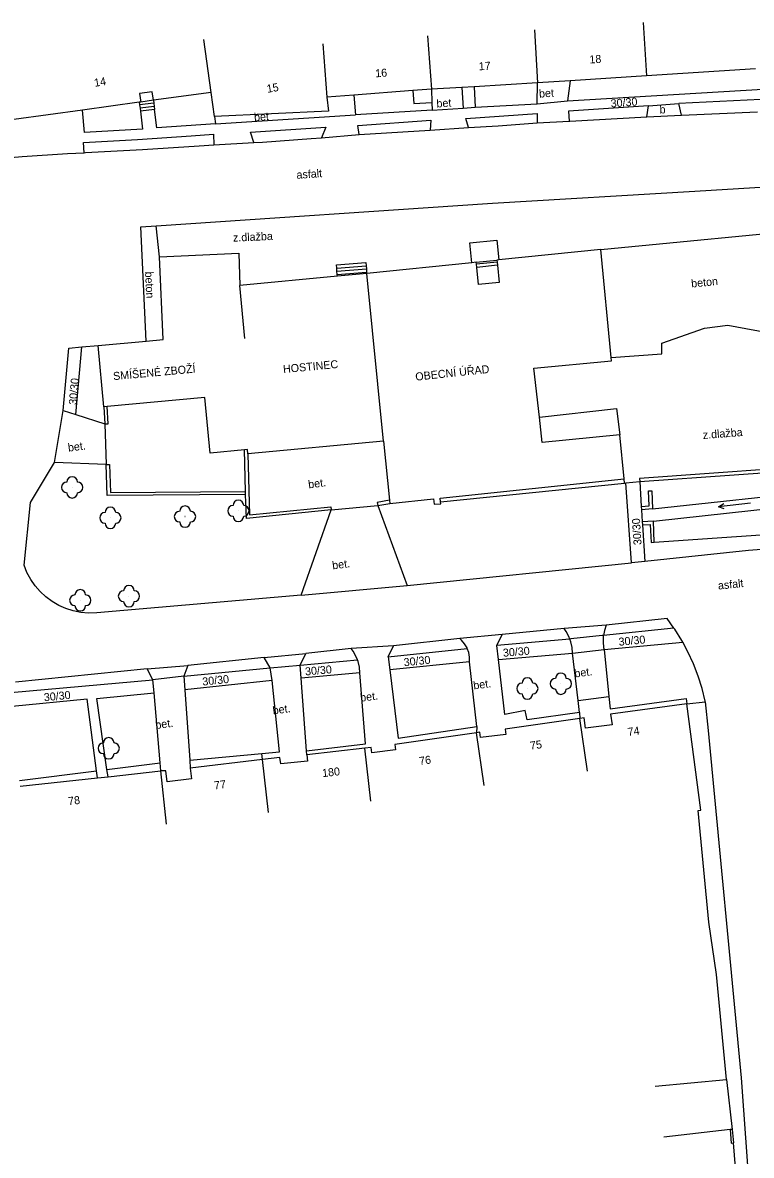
# Model space of a CAD drawing. Extents: x -544674 to -541478, y -1199076 to -1195527.
# Drawn here: x -541857.3 to -541789, y -1198842.7 to -1198736.5 of the extents above; entities that cross this region are included whole.
import ezdxf

# ---------------------------------------------------------------- set-up
doc = ezdxf.new("R2010")
doc.units = 0
for name, color, linetype in [('BUDOVY_MĚŘ', 7, 'Continuous'), ('POMOC_POPIS', 7, 'Continuous'), ('ROZHRANÍ_PLOCH', 7, 'Continuous'), ('ZELEŇ', 7, 'Continuous'), ('ZN_DOPLŇKOVÉ', 7, 'Continuous'), ('ZN_KULTUR', 7, 'Continuous'), ('Č_POPIS_ORIENT', 7, 'Continuous')]:
    doc.layers.add(name, color=color, linetype=linetype)

msp = doc.modelspace()

# ---------------------------------------------------------------- linework, layer by layer
at = {"layer": 'BUDOVY_MĚŘ'}
for points in [[(-541799.16, -1198736.54), (-541798.84, -1198741.53)], [(-541809.36, -1198737.2), (-541809.06, -1198742.19)], [(-541839.64, -1198743.08), (-541840.32, -1198738.13)], [(-541829.17, -1198738.53), (-541828.79, -1198743.52)], [(-541819.37, -1198737.79), (-541818.99, -1198742.78)], [(-541798.84, -1198741.53), (-541805.99, -1198741.99)], [(-541820.75, -1198742.91), (-541826.28, -1198743.33)], [(-541818.99, -1198742.78), (-541820.75, -1198742.91)], [(-541816.15, -1198742.61), (-541818.99, -1198742.78)], [(-541814.99, -1198742.54), (-541816.15, -1198742.61)], [(-541809.06, -1198742.19), (-541814.99, -1198742.54)], [(-541805.99, -1198741.99), (-541809.06, -1198742.19)], [(-541846.38, -1198744), (-541851.69, -1198744.73)], [(-541846.24, -1198743.98), (-541846.38, -1198744)], [(-541845.05, -1198743.82), (-541845.16, -1198743.03), (-541846.35, -1198743.19), (-541846.24, -1198743.98)], [(-541845.05, -1198743.82), (-541846.24, -1198743.98)], [(-541839.64, -1198743.08), (-541845.05, -1198743.82)], [(-541839.33, -1198745.35), (-541839.64, -1198743.08)], [(-541828.79, -1198743.52), (-541828.64, -1198744.85), (-541839.33, -1198745.35)], [(-541826.28, -1198743.33), (-541828.79, -1198743.52)], [(-541851.69, -1198744.73), (-541858.14, -1198745.62)], [(-541803.12, -1198757.8), (-541812.69, -1198758.78)], [(-541802.17, -1198767.94), (-541803.12, -1198757.8)], [(-541845.74, -1198766.38), (-541844.14, -1198766.23), (-541844.48, -1198758.49)], [(-541844.48, -1198758.49), (-541837.06, -1198758.16), (-541836.95, -1198761.17)], [(-541812.69, -1198758.78), (-541812.87, -1198758.8)], [(-541812.87, -1198758.8), (-541812.85, -1198758.99)], [(-541815.22, -1198759.04), (-541825.06, -1198760.04)], [(-541814.8, -1198759), (-541815.22, -1198759.04)], [(-541814.78, -1198759.18), (-541814.8, -1198759)], [(-541814.75, -1198759.48), (-541814.78, -1198759.18)], [(-541812.82, -1198759.28), (-541812.65, -1198760.9), (-541814.58, -1198761.09), (-541814.75, -1198759.48)], [(-541812.85, -1198758.99), (-541812.82, -1198759.28)], [(-541827.81, -1198760.3), (-541836.95, -1198761.17)], [(-541825.06, -1198760.04), (-541827.81, -1198760.3)], [(-541823.49, -1198775.77), (-541825.06, -1198760.04)], [(-541836.48, -1198766.15), (-541836.95, -1198761.17)], [(-541850.23, -1198766.8), (-541845.74, -1198766.38)], [(-541849.69, -1198772.55), (-541850.23, -1198766.8)], [(-541808.89, -1198773.51), (-541809.41, -1198768.92), (-541802.14, -1198768.24), (-541802.17, -1198767.94)], [(-541849.39, -1198772.52), (-541849.69, -1198772.55)], [(-541836.52, -1198776.59), (-541839.73, -1198776.89), (-541840.22, -1198771.67), (-541849.39, -1198772.52)], [(-541801.36, -1198775.18), (-541808.62, -1198775.9), (-541808.89, -1198773.51)], [(-541823.49, -1198775.77), (-541836.21, -1198776.96)], [(-541823.49, -1198775.77), (-541822.93, -1198781.3)], [(-541800.95, -1198779.3), (-541801.36, -1198775.18)], [(-541836.21, -1198776.96), (-541836.25, -1198776.56), (-541836.52, -1198776.59)], [(-541818.15, -1198781.46), (-541818.19, -1198781.1), (-541800.95, -1198779.3)], [(-541822.9, -1198781.6), (-541818.81, -1198781.17), (-541818.75, -1198781.68), (-541818.13, -1198781.63), (-541818.15, -1198781.46)], [(-541822.93, -1198781.3), (-541822.9, -1198781.6)], [(-541795.07, -1198800.4), (-541802.22, -1198801.36), (-541802.08, -1198802.35), (-541804.56, -1198802.68), (-541804.69, -1198801.69), (-541805.09, -1198801.75)], [(-541791.35, -1198835.59), (-541792.29, -1198825.76), (-541793.02, -1198820.86), (-541794, -1198810.37), (-541793.75, -1198810.34), (-541795.07, -1198800.4)], [(-541805.09, -1198801.75), (-541812.1, -1198802.76), (-541812.03, -1198803.25), (-541814.4, -1198803.54), (-541814.47, -1198803.05), (-541814.77, -1198803.09)], [(-541804.38, -1198806.7), (-541805.09, -1198801.75)], [(-541814.77, -1198803.09), (-541822.43, -1198804.19), (-541822.36, -1198804.69), (-541824.59, -1198804.97), (-541824.64, -1198804.47), (-541825.24, -1198804.54)], [(-541814.06, -1198808.04), (-541814.77, -1198803.09)], [(-541825.24, -1198804.54), (-541830.69, -1198805.17)], [(-541824.67, -1198809.51), (-541825.24, -1198804.54)], [(-541834.82, -1198805.59), (-541841.6, -1198806.43)], [(-541830.69, -1198805.17), (-541830.62, -1198805.77), (-541833.12, -1198806.01), (-541833.19, -1198805.41), (-541834.82, -1198805.59)], [(-541834.27, -1198810.56), (-541834.82, -1198805.59)], [(-541849.3, -1198807.22), (-541844.36, -1198806.68)], [(-541841.6, -1198806.43), (-541841.48, -1198807.42), (-541843.76, -1198807.69), (-541843.89, -1198806.65), (-541844.36, -1198806.68)], [(-541843.82, -1198811.65), (-541844.36, -1198806.68)], [(-541857.54, -1198808.11), (-541850.3, -1198807.33)], [(-541850.3, -1198807.33), (-541849.3, -1198807.22)], [(-541798.03, -1198836.23), (-541791.35, -1198835.59)], [(-541791.35, -1198835.59), (-541790.81, -1198840.27)], [(-541791.01, -1198840.29), (-541797.23, -1198841.01)], [(-541790.81, -1198840.27), (-541791.01, -1198840.29)]]:
    msp.add_lwpolyline(points, dxfattribs=at)
at = {"layer": 'ROZHRANÍ_PLOCH'}
for points in [[(-541820.75, -1198742.91), (-541820.66, -1198744.13), (-541818.95, -1198744.03)], [(-541818.99, -1198742.78), (-541818.95, -1198744.03)], [(-541816.15, -1198742.61), (-541816.03, -1198744.54)], [(-541814.99, -1198742.54), (-541814.9, -1198744.46)], [(-541809.08, -1198744.15), (-541809.06, -1198742.19)], [(-541805.99, -1198741.99), (-541806.25, -1198743.88)], [(-541806.25, -1198743.88), (-541787.96, -1198742.78)], [(-541846.38, -1198744), (-541846.34, -1198744.25)], [(-541845.05, -1198743.82), (-541845.02, -1198744.09)], [(-541826.28, -1198743.33), (-541826.12, -1198745.19)], [(-541818.95, -1198744.03), (-541818.93, -1198744.73)], [(-541809.08, -1198744.15), (-541806.25, -1198743.88)], [(-541788.15, -1198743.74), (-541795.83, -1198744.13)], [(-541846.26, -1198744.84), (-541846.06, -1198746.52), (-541851.52, -1198746.84), (-541851.69, -1198744.73)], [(-541845.02, -1198744.09), (-541846.34, -1198744.25)], [(-541846.34, -1198744.25), (-541846.3, -1198744.54)], [(-541844.98, -1198744.39), (-541846.3, -1198744.54)], [(-541846.3, -1198744.54), (-541846.26, -1198744.84)], [(-541844.94, -1198744.68), (-541846.26, -1198744.84)], [(-541845.02, -1198744.09), (-541844.98, -1198744.39)], [(-541844.98, -1198744.39), (-541844.94, -1198744.68)], [(-541839.22, -1198746.03), (-541844.74, -1198746.39), (-541844.94, -1198744.68)], [(-541818.93, -1198744.73), (-541826.12, -1198745.19)], [(-541818.93, -1198744.73), (-541816.03, -1198744.54)], [(-541816.03, -1198744.54), (-541814.9, -1198744.46)], [(-541815.53, -1198746.38), (-541815.78, -1198745.52), (-541809.11, -1198745.05), (-541809.09, -1198745.93)], [(-541814.9, -1198744.46), (-541809.08, -1198744.15)], [(-541798.66, -1198744.34), (-541806.15, -1198744.85), (-541806.09, -1198745.77)], [(-541798.81, -1198745.36), (-541798.66, -1198744.34)], [(-541798.66, -1198744.34), (-541795.83, -1198744.13)], [(-541795.56, -1198745.22), (-541795.83, -1198744.13)], [(-541795.56, -1198745.22), (-541788.46, -1198744.89)], [(-541839.33, -1198745.35), (-541839.22, -1198746.03)], [(-541839.22, -1198746.03), (-541826.12, -1198745.19)], [(-541825.76, -1198747.01), (-541825.9, -1198746.17), (-541819.07, -1198745.68), (-541819.11, -1198746.61)], [(-541815.53, -1198746.38), (-541812.76, -1198746.2), (-541809.09, -1198745.93)], [(-541809.09, -1198745.93), (-541806.09, -1198745.77)], [(-541806.09, -1198745.77), (-541806.02, -1198745.77), (-541798.81, -1198745.36)], [(-541798.81, -1198745.36), (-541795.56, -1198745.22)], [(-541851.55, -1198748.73), (-541851.59, -1198747.77), (-541846.55, -1198747.5), (-541841.52, -1198747.15), (-541839.42, -1198746.98), (-541839.4, -1198747.98)], [(-541835.64, -1198747.78), (-541835.96, -1198746.79), (-541828.9, -1198746.35), (-541829.29, -1198747.32)], [(-541829.29, -1198747.32), (-541825.76, -1198747.01)], [(-541825.76, -1198747.01), (-541819.11, -1198746.61)], [(-541819.11, -1198746.61), (-541815.53, -1198746.38)], [(-541851.55, -1198748.73), (-541851.4, -1198748.72), (-541846.08, -1198748.44), (-541840.76, -1198748.08), (-541839.4, -1198747.98)], [(-541839.4, -1198747.98), (-541835.64, -1198747.78)], [(-541835.64, -1198747.78), (-541834.84, -1198747.74), (-541830.28, -1198747.41), (-541829.29, -1198747.32)], [(-541867.92, -1198750.18), (-541865.85, -1198749.92), (-541861.61, -1198749.47), (-541857.36, -1198749.1), (-541853.1, -1198748.81), (-541851.55, -1198748.73)], [(-541844.79, -1198755.59), (-541813.27, -1198753.45), (-541794.31, -1198752.32), (-541783.08, -1198751.66)], [(-541845.74, -1198766.38), (-541846.22, -1198755.69), (-541844.79, -1198755.59)], [(-541844.48, -1198758.49), (-541844.79, -1198755.59)], [(-541803.12, -1198757.8), (-541781.8, -1198755.74)], [(-541815.22, -1198759.04), (-541815.41, -1198757.19), (-541812.88, -1198756.93), (-541812.69, -1198758.78)], [(-541814.8, -1198759), (-541812.87, -1198758.8)], [(-541827.88, -1198759.54), (-541827.91, -1198759.24), (-541825.16, -1198759.02), (-541825.13, -1198759.32)], [(-541827.88, -1198759.54), (-541825.13, -1198759.32)], [(-541827.85, -1198759.84), (-541827.88, -1198759.54)], [(-541827.85, -1198759.84), (-541825.1, -1198759.62)], [(-541827.82, -1198760.14), (-541827.85, -1198759.84)], [(-541827.82, -1198760.14), (-541825.07, -1198759.92)], [(-541825.13, -1198759.32), (-541825.1, -1198759.62)], [(-541825.1, -1198759.62), (-541825.07, -1198759.92)], [(-541825.07, -1198759.92), (-541825.06, -1198760.04)], [(-541812.85, -1198758.99), (-541814.78, -1198759.18)], [(-541812.82, -1198759.28), (-541814.75, -1198759.48)], [(-541827.81, -1198760.3), (-541827.82, -1198760.14)], [(-541802.17, -1198767.94), (-541797.43, -1198767.58), (-541797.4, -1198766.58), (-541793.42, -1198765.18), (-541791.22, -1198764.9), (-541786.68, -1198765.73), (-541786.58, -1198767.24), (-541780.84, -1198767.12)], [(-541853.49, -1198772.88), (-541852.98, -1198767.05), (-541851.77, -1198766.94)], [(-541852.32, -1198773.26), (-541851.77, -1198766.94)], [(-541851.77, -1198766.94), (-541850.23, -1198766.8)], [(-541808.89, -1198773.51), (-541801.67, -1198772.7), (-541801.36, -1198775.18)], [(-541854.32, -1198777.78), (-541853.49, -1198772.88)], [(-541853.49, -1198772.88), (-541852.32, -1198773.26)], [(-541852.32, -1198773.26), (-541849.6, -1198774.15)], [(-541849.6, -1198774.15), (-541849.47, -1198777.95)], [(-541831.21, -1198790.19), (-541850.36, -1198791.87), (-541851.13, -1198791.89), (-541851.85, -1198791.82), (-541852.56, -1198791.68), (-541853.26, -1198791.46), (-541853.92, -1198791.16), (-541854.55, -1198790.8), (-541855.13, -1198790.36), (-541855.67, -1198789.87), (-541856.14, -1198789.32), (-541856.55, -1198788.72), (-541856.9, -1198788.08), (-541857.17, -1198787.4), (-541856.56, -1198781.51), (-541854.32, -1198777.78)], [(-541849.47, -1198777.95), (-541854.32, -1198777.78)], [(-541710.2, -1198778.44), (-541725.87, -1198780), (-541761.28, -1198783.4), (-541783.3, -1198785.55), (-541789.31, -1198786.01), (-541799.01, -1198787.05)], [(-541818.15, -1198781.46), (-541800.91, -1198779.69)], [(-541800.91, -1198779.69), (-541800.95, -1198779.3)], [(-541800.91, -1198779.69), (-541800.8, -1198779.68)], [(-541800.8, -1198779.68), (-541799.49, -1198779.54)], [(-541800.27, -1198787.18), (-541800.8, -1198779.68)], [(-541799.49, -1198779.54), (-541799.34, -1198781.89)], [(-541831.21, -1198790.19), (-541828.39, -1198782.21)], [(-541828.39, -1198782.21), (-541824.03, -1198781.8)], [(-541824.03, -1198781.8), (-541821.27, -1198789.28)], [(-541799.34, -1198781.89), (-541799.32, -1198782.19)], [(-541799.32, -1198782.19), (-541799.25, -1198783.32)], [(-541799.25, -1198783.32), (-541799.23, -1198783.62)], [(-541799.23, -1198783.62), (-541799.01, -1198787.05)], [(-541821.27, -1198789.28), (-541800.27, -1198787.18)], [(-541799.01, -1198787.05), (-541800.27, -1198787.18)], [(-541831.21, -1198790.19), (-541821.27, -1198789.28)], [(-541796.28, -1198793.29), (-541796.93, -1198792.4), (-541802.62, -1198793)], [(-541812.36, -1198793.89), (-541816.33, -1198794.27)], [(-541812.86, -1198794.92), (-541812.36, -1198793.89)], [(-541806.58, -1198793.33), (-541812.36, -1198793.89)], [(-541802.62, -1198793), (-541806.58, -1198793.33)], [(-541806.03, -1198794.31), (-541806.12, -1198794.08), (-541806.37, -1198793.61), (-541806.58, -1198793.33)], [(-541802.62, -1198793), (-541802.8, -1198793.51), (-541802.89, -1198793.98)], [(-541796.28, -1198793.29), (-541802.89, -1198793.98)], [(-541795.46, -1198794.6), (-541795.55, -1198794.44), (-541796.21, -1198793.4), (-541796.28, -1198793.29)], [(-541822.57, -1198794.95), (-541826.53, -1198795.2)], [(-541823.04, -1198795.97), (-541822.57, -1198794.95)], [(-541816.33, -1198794.27), (-541822.57, -1198794.95)], [(-541815.64, -1198795.19), (-541815.66, -1198795.14), (-541815.89, -1198794.75), (-541816.18, -1198794.41), (-541816.33, -1198794.27)], [(-541806.03, -1198794.31), (-541812.86, -1198794.92)], [(-541812.71, -1198796.22), (-541812.86, -1198794.92)], [(-541802.89, -1198793.98), (-541802.99, -1198793.99), (-541805.95, -1198794.3), (-541806.03, -1198794.31)], [(-541805.8, -1198795.63), (-541805.83, -1198795.1), (-541805.93, -1198794.58), (-541806.03, -1198794.31)], [(-541802.89, -1198793.98), (-541802.9, -1198794.04), (-541802.92, -1198794.58), (-541802.87, -1198795.11), (-541802.83, -1198795.28)], [(-541802.83, -1198795.28), (-541795.46, -1198794.6)], [(-541793.34, -1198800.21), (-541793.35, -1198800.15), (-541793.64, -1198798.96), (-541794.01, -1198797.78), (-541794.45, -1198796.64), (-541794.97, -1198795.52), (-541795.46, -1198794.6)], [(-541834.66, -1198796.05), (-541841.82, -1198796.78)], [(-541834.66, -1198796.05), (-541830.78, -1198795.68)], [(-541834.12, -1198797), (-541834.66, -1198796.05)], [(-541831.3, -1198796.75), (-541830.78, -1198795.68)], [(-541826.53, -1198795.2), (-541830.78, -1198795.68)], [(-541825.94, -1198796.26), (-541826.07, -1198795.92), (-541826.34, -1198795.45), (-541826.53, -1198795.2)], [(-541823.04, -1198795.97), (-541815.64, -1198795.19)], [(-541823.04, -1198795.97), (-541822.89, -1198797.21)], [(-541815.44, -1198796.45), (-541815.44, -1198796), (-541815.51, -1198795.56), (-541815.64, -1198795.19)], [(-541812.71, -1198796.22), (-541805.8, -1198795.63)], [(-541805.8, -1198795.63), (-541802.83, -1198795.28)], [(-541805.26, -1198800.07), (-541805.8, -1198795.63)], [(-541802.83, -1198795.28), (-541802.37, -1198799.71)], [(-541845.65, -1198797.1), (-541857.97, -1198798.34)], [(-541845.65, -1198797.1), (-541841.82, -1198796.78)], [(-541845.1, -1198798.13), (-541845.65, -1198797.1)], [(-541841.82, -1198796.78), (-541842.2, -1198797.78)], [(-541842.2, -1198797.78), (-541834.12, -1198797)], [(-541834.12, -1198797), (-541831.3, -1198796.75)], [(-541833.91, -1198798.2), (-541834.12, -1198797)], [(-541831.3, -1198796.75), (-541825.94, -1198796.26)], [(-541831.21, -1198797.97), (-541831.3, -1198796.75)], [(-541825.71, -1198797.49), (-541825.75, -1198796.95), (-541825.88, -1198796.42), (-541825.94, -1198796.26)], [(-541815.44, -1198796.45), (-541822.89, -1198797.21)], [(-541814.75, -1198802.52), (-541815.44, -1198796.45)], [(-541805.12, -1198801.21), (-541810.04, -1198801.88), (-541810.21, -1198801.01), (-541812.13, -1198801.38), (-541812.71, -1198796.22)], [(-541858.42, -1198799.32), (-541845.1, -1198798.13)], [(-541842.2, -1198797.78), (-541845.1, -1198798.13)], [(-541844.99, -1198799.36), (-541845.1, -1198798.13)], [(-541842.2, -1198797.78), (-541842.11, -1198799.06)], [(-541825.71, -1198797.49), (-541831.21, -1198797.97)], [(-541830.72, -1198804.78), (-541831.21, -1198797.97)], [(-541830.72, -1198804.78), (-541825.19, -1198804.12), (-541825.71, -1198797.49)], [(-541822.89, -1198797.21), (-541822.12, -1198803.61), (-541814.75, -1198802.52)], [(-541833.91, -1198798.2), (-541842.11, -1198799.06)], [(-541842.11, -1198799.06), (-541841.65, -1198805.67)], [(-541834.89, -1198805.03), (-541833.24, -1198804.87), (-541833.91, -1198798.2)], [(-541850.39, -1198806.67), (-541851.27, -1198799.96), (-541858.29, -1198800.64)], [(-541849.4, -1198806.55), (-541850.35, -1198799.88), (-541844.99, -1198799.36)], [(-541844.42, -1198805.93), (-541844.99, -1198799.36)], [(-541805.26, -1198800.07), (-541802.37, -1198799.71)], [(-541805.12, -1198801.21), (-541805.26, -1198800.07)], [(-541802.37, -1198799.71), (-541802.25, -1198800.86), (-541795.14, -1198799.9), (-541795.07, -1198800.4)], [(-541795.07, -1198800.4), (-541793.34, -1198800.21)], [(-541793.34, -1198800.21), (-541793.06, -1198802.9), (-541789.99, -1198835.43), (-541789.35, -1198844.08), (-541788.68, -1198854.12), (-541788.1, -1198864.17), (-541787.59, -1198874.22), (-541786.75, -1198895.27), (-541786.48, -1198902.47), (-541785.27, -1198936.71), (-541785.21, -1198938.09), (-541785.23, -1198939.47), (-541785.28, -1198940.29)], [(-541805.12, -1198801.21), (-541805.09, -1198801.75)], [(-541814.75, -1198802.52), (-541814.77, -1198803.09)], [(-541841.65, -1198805.67), (-541834.89, -1198805.03)], [(-541834.82, -1198805.59), (-541834.89, -1198805.03)], [(-541830.69, -1198805.17), (-541830.72, -1198804.78)], [(-541857.6, -1198807.57), (-541850.39, -1198806.67)], [(-541850.3, -1198807.33), (-541850.39, -1198806.67)], [(-541849.4, -1198806.55), (-541844.42, -1198805.93)], [(-541849.3, -1198807.22), (-541849.4, -1198806.55)], [(-541844.36, -1198806.68), (-541844.42, -1198805.93)], [(-541841.65, -1198805.67), (-541841.6, -1198806.43)]]:
    msp.add_lwpolyline(points, dxfattribs=at)
at = {"layer": 'ZELEŇ'}
for centre in [(-541852.66, -1198780.1), (-541849.08, -1198782.95), (-541842.09, -1198782.84), (-541837.09, -1198782.3), (-541851.9, -1198790.68), (-541847.34, -1198790.29), (-541810.01, -1198798.95), (-541806.87, -1198798.5), (-541849.24, -1198804.55)]:
    msp.add_circle(centre, 0.0005, dxfattribs=at)
for centre, start, end in [((-541853.16, -1198780.1), 89.99999, 269.99999), ((-541852.66, -1198779.6), 0, 179.99999), ((-541852.16, -1198780.1), 270, 89.99999), ((-541852.66, -1198780.6), 179.99999, 359.99999), ((-541849.08, -1198782.45), 0, 179.99999), ((-541842.09, -1198782.34), 0, 179.99999), ((-541837.59, -1198782.3), 89.99999, 269.99999), ((-541837.09, -1198781.8), 0, 179.99999), ((-541836.59, -1198782.3), 270, 89.99999), ((-541849.58, -1198782.95), 89.99999, 269.99999), ((-541848.58, -1198782.95), 270, 89.99999), ((-541842.59, -1198782.84), 89.99999, 269.99999), ((-541841.59, -1198782.84), 270, 89.99999), ((-541837.09, -1198782.8), 179.99999, 359.99999), ((-541849.08, -1198783.45), 179.99999, 359.99999), ((-541842.09, -1198783.34), 179.99999, 359.99999), ((-541851.9, -1198790.18), 0, 179.99999), ((-541847.34, -1198789.79), 0, 179.99999), ((-541852.4, -1198790.68), 89.99999, 269.99999), ((-541851.4, -1198790.68), 270, 89.99999), ((-541847.84, -1198790.29), 89.99999, 269.99999), ((-541846.84, -1198790.29), 270, 89.99999), ((-541851.9, -1198791.18), 179.99999, 359.99999), ((-541847.34, -1198790.79), 179.99999, 359.99999), ((-541810.01, -1198798.45), 0, 179.99999), ((-541807.37, -1198798.5), 89.99999, 269.99999), ((-541806.87, -1198798), 0, 179.99999), ((-541806.37, -1198798.5), 270, 89.99999), ((-541810.51, -1198798.95), 89.99999, 269.99999), ((-541809.51, -1198798.95), 270, 89.99999), ((-541806.87, -1198799), 179.99999, 359.99999), ((-541810.01, -1198799.45), 179.99999, 359.99999), ((-541849.74, -1198804.55), 89.99999, 269.99999), ((-541849.24, -1198804.05), 0, 179.99999), ((-541848.74, -1198804.55), 270, 89.99999), ((-541849.24, -1198805.05), 179.99999, 359.99999)]:
    msp.add_arc(centre, 0.5, start, end, dxfattribs=at)
at = {"layer": 'ZN_DOPLŇKOVÉ'}
for points in [[(-541788.65, -1198740.86), (-541798.84, -1198741.53)], [(-541799.49, -1198779.54), (-541764.13, -1198777.04), (-541722.38, -1198773.46), (-541708.23, -1198772.31), (-541706.34, -1198755.86)], [(-541849.69, -1198772.55), (-541849.6, -1198774.15)], [(-541849.6, -1198774.15), (-541849.3, -1198774.13), (-541849.39, -1198772.52)], [(-541836.42, -1198780.48), (-541836.52, -1198776.59)], [(-541836.21, -1198776.96), (-541836.04, -1198782.68), (-541828.42, -1198781.91), (-541828.39, -1198782.21)], [(-541798.28, -1198782.12), (-541782.07, -1198780.37), (-541760.26, -1198778.19), (-541725.97, -1198776.3)], [(-541849.47, -1198777.95), (-541849.17, -1198777.94), (-541849.08, -1198780.57), (-541836.42, -1198780.48)], [(-541836.41, -1198780.78), (-541849.37, -1198780.87), (-541849.47, -1198777.95)], [(-541779.97, -1198777.85), (-541780.35, -1198777.88), (-541799.51, -1198779.25), (-541799.49, -1198779.54)], [(-541798.21, -1198783.25), (-541781.95, -1198781.49), (-541760.17, -1198779.32), (-541725.96, -1198777.43)], [(-541798.13, -1198785.24), (-541782.72, -1198784.17), (-541760.3, -1198782.17), (-541725.93, -1198779.32), (-541725.56, -1198778.56)], [(-541836.41, -1198780.78), (-541836.42, -1198780.48)], [(-541828.39, -1198782.21), (-541836.33, -1198783.01), (-541836.41, -1198780.78)], [(-541799.34, -1198781.89), (-541798.59, -1198781.84), (-541798.66, -1198780.42), (-541798.36, -1198780.41), (-541798.28, -1198782.12), (-541799.32, -1198782.19)], [(-541822.93, -1198781.3), (-541824.08, -1198781.5), (-541824.03, -1198781.8)], [(-541824.03, -1198781.8), (-541822.9, -1198781.6)], [(-541799.23, -1198783.62), (-541798.5, -1198783.57), (-541798.43, -1198785.25), (-541798.13, -1198785.24), (-541798.21, -1198783.25), (-541799.25, -1198783.32)], [(-541791.01, -1198840.29), (-541790.91, -1198841.56), (-541790.71, -1198841.54)], [(-541790.81, -1198840.27), (-541790.71, -1198841.54)], [(-541790.5, -1198843.85), (-541790.71, -1198841.54)]]:
    msp.add_lwpolyline(points, dxfattribs=at)
at = {"layer": 'ZN_KULTUR'}
msp.add_line((-541789.109, -1198781.589), (-541792.091, -1198781.911), dxfattribs=at)
msp.add_lwpolyline([(-541791.567, -1198782.106), (-541792.091, -1198781.911), (-541791.621, -1198781.609)], dxfattribs=at)

# ---------------------------------------------------------------- texts
at = {"layer": 'POMOC_POPIS'}
for s, rotation, p in [('bet', 3.82999, (-541808.9, -1198743.57)), ('bet', 3.82999, (-541818.51, -1198744.5)), ('30/30', 4.31999, (-541802.18, -1198744.49)), ('bet', 3.56999, (-541835.6, -1198745.77)), ('b', 2.51001, (-541797.61, -1198745.06)), ('asfalt', 3.90001, (-541831.62, -1198751.18)), ('z.dlažba', 2.55001, (-541837.58, -1198757.07)), ('beton', 272.53998, (-541845.83, -1198759.89)), ('beton', 5.51999, (-541794.63, -1198761.37)), ('SMÍŠENÉ ZBOŽÍ', 5.31, (-541848.79, -1198770.05)), ('HOSTINEC', 5.40998, (-541832.87, -1198769.39)), ('OBECNÍ ÚŘAD', 6.06, (-541820.47, -1198770.1)), ('30/30', 85.02, (-541852.24, -1198772.39)), ('z.dlažba', 4.27999, (-541793.55, -1198775.56)), ('bet.', 7.46003, (-541853.01, -1198776.75)), ('bet.', 7.46003, (-541830.5, -1198780.2)), ('30/30', 93.67001, (-541799.31, -1198785.48)), ('bet.', 7.46003, (-541828.25, -1198787.79)), ('asfalt', 5.85998, (-541792.12, -1198789.68)), ('30/30', 5.29, (-541801.43, -1198794.95)), ('30/30', 5.79002, (-541821.56, -1198796.87)), ('30/30', 4.86, (-541812.27, -1198795.98)), ('30/30', 4.93998, (-541830.81, -1198797.73)), ('bet.', 7.46003, (-541805.56, -1198797.92)), ('30/30', 5.96999, (-541840.43, -1198798.68)), ('bet.', 7.46003, (-541815.03, -1198799.04)), ('30/30', 5.49999, (-541855.28, -1198800.15)), ('bet.', 7.46003, (-541825.63, -1198800.19)), ('bet.', 7.46003, (-541833.83, -1198801.38)), ('bet.', 7.46003, (-541844.82, -1198802.75))]:
    msp.add_text(s, height=0.75, rotation=rotation, dxfattribs=at).set_placement(p)
at = {"layer": 'Č_POPIS_ORIENT'}
for s, rotation, p in [('18', 3.69002, (-541804.18, -1198740.37)), ('16', 4.31999, (-541824.24, -1198741.67)), ('17', 3.39999, (-541814.55, -1198741.01)), ('14', 9.62002, (-541850.54, -1198742.56)), ('15', 9.62002, (-541834.37, -1198743.12)), ('74', 7.99001, (-541800.56, -1198803.4)), ('75', 8.21003, (-541809.71, -1198804.69)), ('76', 8.16998, (-541820.1, -1198806.13)), ('180', 6.58999, (-541829.2, -1198807.26)), ('77', 7.05999, (-541839.32, -1198808.41)), ('78', 6.17998, (-541853, -1198809.88))]:
    msp.add_text(s, height=0.75, rotation=rotation, dxfattribs=at).set_placement(p)

doc.saveas('drawing.dxf')
